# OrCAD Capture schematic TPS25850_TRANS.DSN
size B
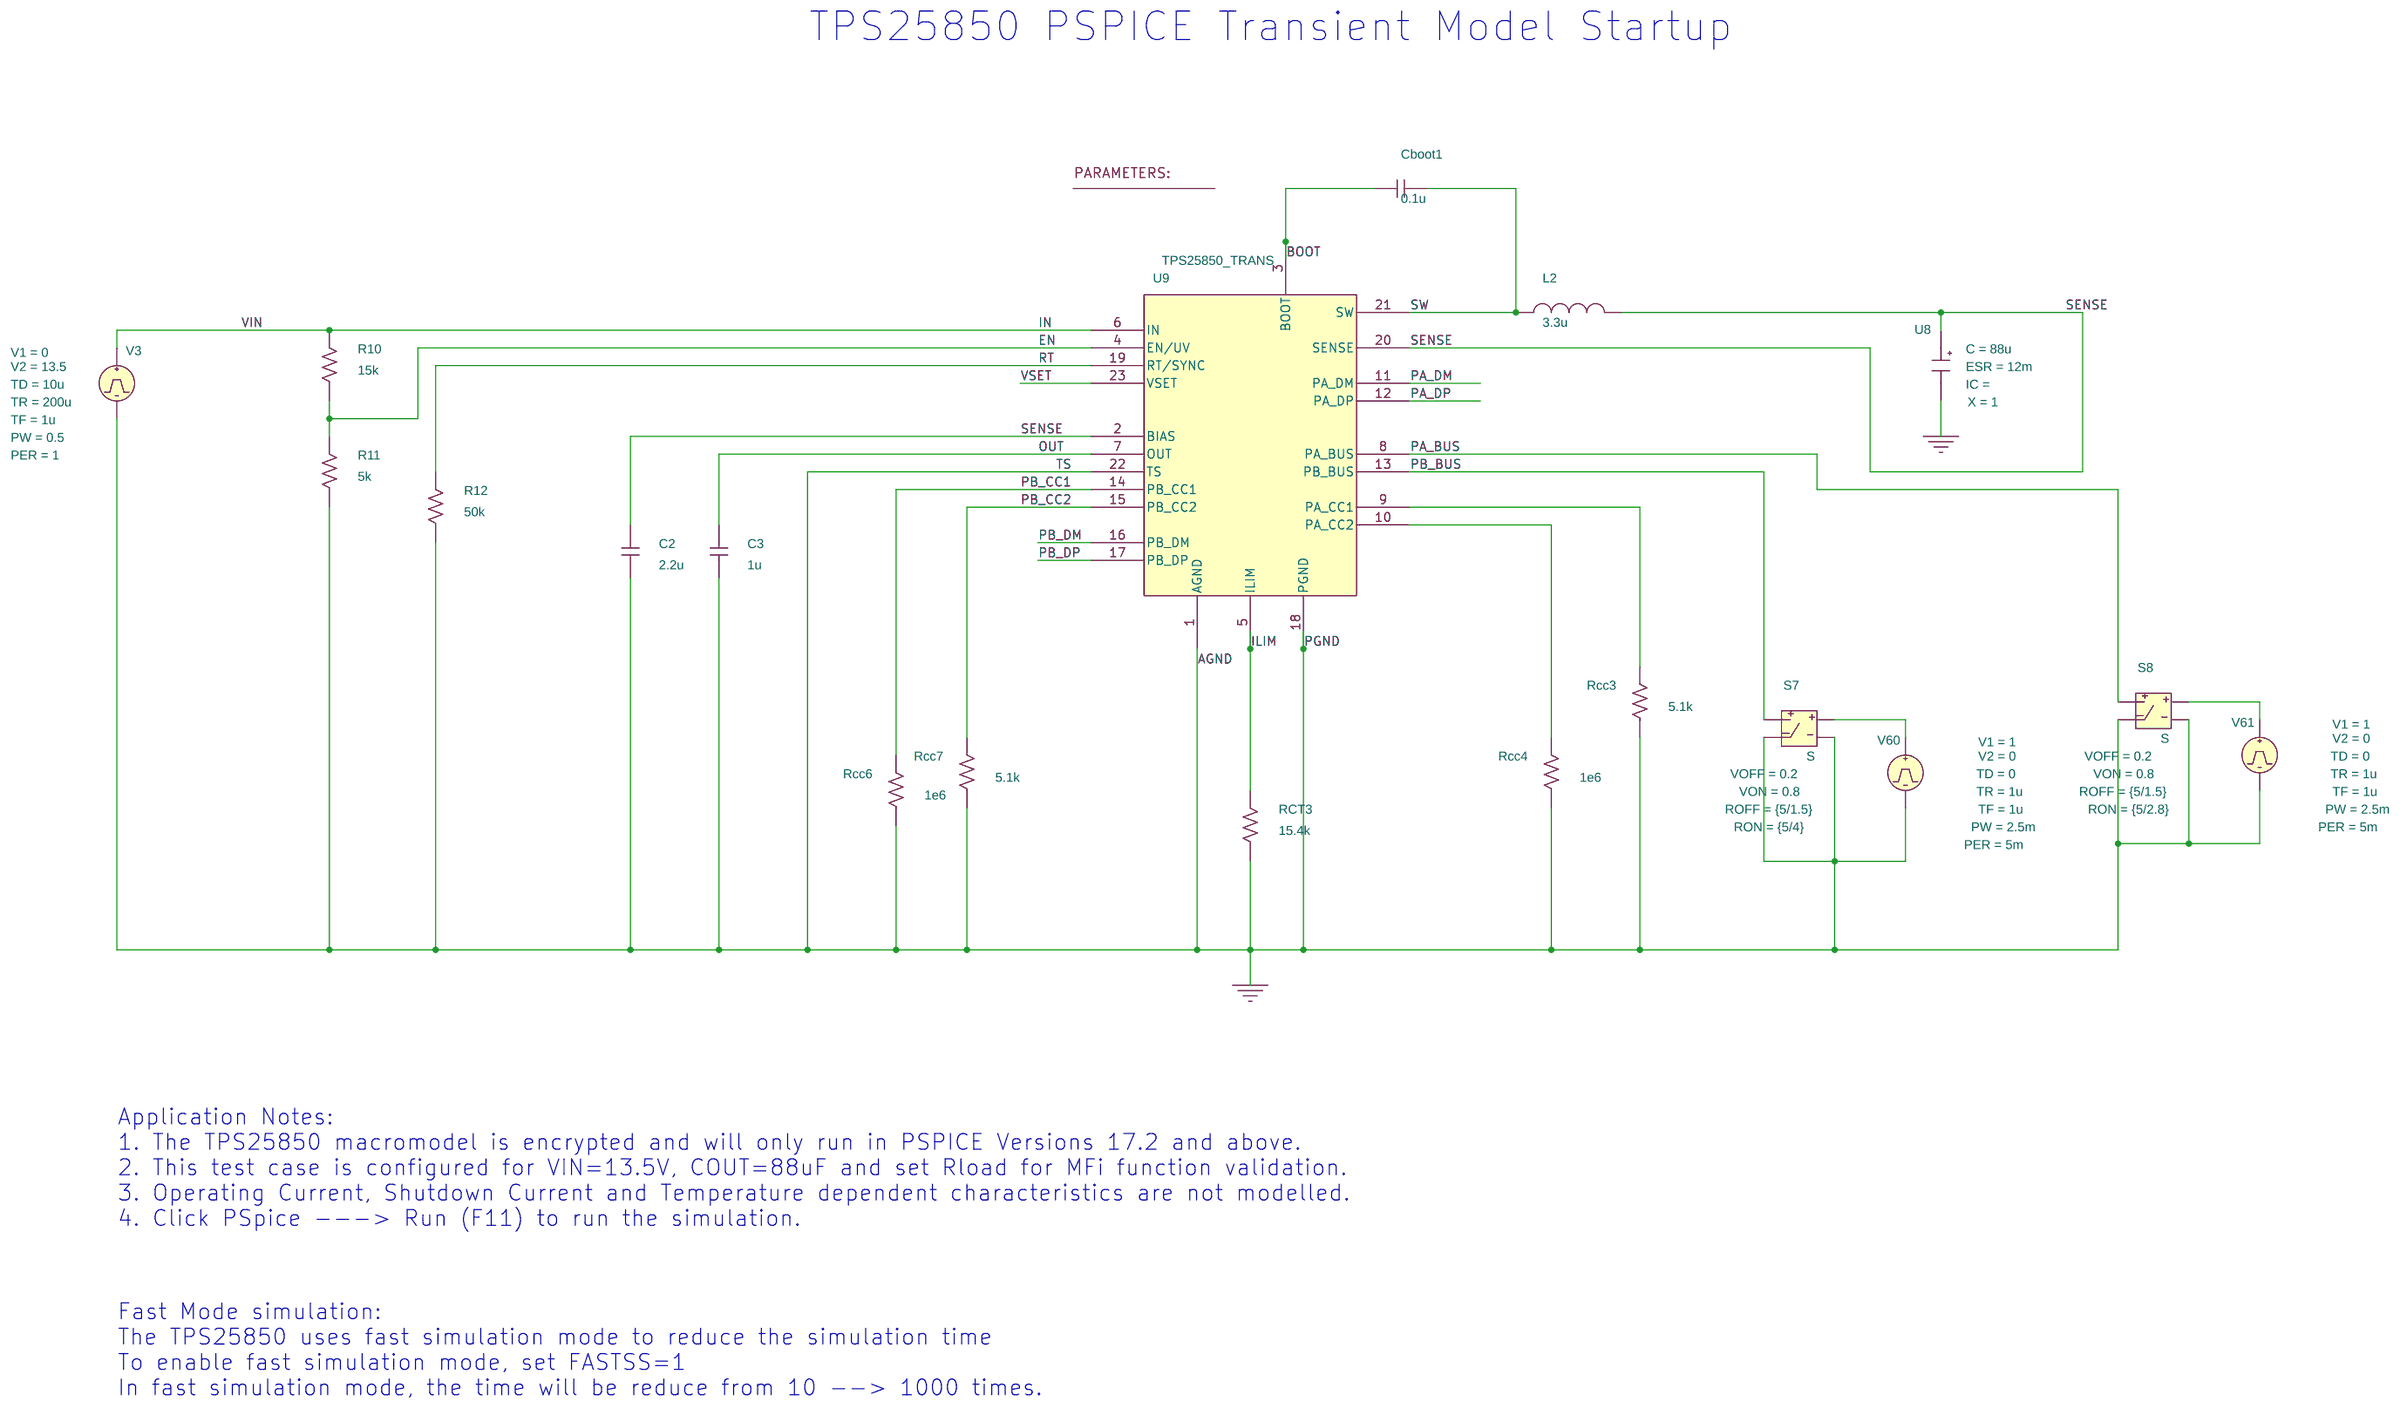
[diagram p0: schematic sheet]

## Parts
1  PARAM
C2  2.2u  [RAD/CK05]
C3  1u  [RAD/CK05]
Cboot1  0.1u  [RAD/CK05]
L2  3.3u  [DISC/.350x.175/LS.200x.100/.034]
R10  15k  [AX/RC05]
R11  5k  [AX/RC05]
R12  50k  [AX/RC05]
Rcc3  5.1k  [AX/RC05]
Rcc4  1e6  [AX/RC05]
Rcc6  1e6  [AX/RC05]
Rcc7  5.1k  [AX/RC05]
RCT3  15.4k  [AX/RC05]
S7  S
S8  S
U8  CESR
U9  TPS25850_TRANS
V3  VPULSE
V60  VPULSE
V61  VPULSE

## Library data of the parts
1 = PARAM: MODE: 0; VIN: 10; VOUTIC: 5
C2 C3 Cboot1 = C
L2 = L
R10-R12 Rcc3 Rcc4 Rcc6 Rcc7 RCT3 = R
S7 = S: ROFF: {5/1.5}; RON: {5/4}; VOFF: 0.2; VON: 0.8
S8 = S: ROFF: {5/1.5}; RON: {5/2.8}; VOFF: 0.2; VON: 0.8
U8 = CESR_0: C: 88u; ESR: 12m; X: 1
U9 = TPS25850_TRANS
V3 = VPULSE: PER: 1; PW: 0.5; TD: 10u; TF: 1u; TR: 200u; V1: 0; V2: 13.5
V60 V61 = VPULSE: PER: 5m; PW: 2.5m; TD: 0; TF: 1u; TR: 1u; V1: 1; V2: 0

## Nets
0: C2.1 C3.1 R11.1 R12.1 Rcc3.1 Rcc4.1 Rcc6.1 Rcc7.1 RCT3.1 S7.1(2) S7.3(4) S8.1(2) S8.3(4) U8.2(OUT) U9.1(AGND) U9.18(PGND) U9.22(TS) V3.2(-) V60.2(-) V61.2(-)
BOOT: Cboot1.1 U9.3(BOOT)
EN: R10.1 R11.2 U9.4(EN/UV)
ILIM: RCT3.2 U9.5(ILIM)
IN: R10.2 U9.6(IN) V3.1(+)
OUT: C3.2 U9.7(OUT)
PA_BUS: S8.2(3) U9.8(PA_BUS)
PA_DM: U9.11(PA_DM)
PA_DP: U9.12(PA_DP)
PB_BUS: S7.2(3) U9.13(PB_BUS)
PB_CC1: Rcc6.2 U9.14(PB_CC1)
PB_CC2: Rcc7.2 U9.15(PB_CC2)
PB_DM: U9.16(PB_DM)
PB_DP: U9.17(PB_DP)
RT: R12.2 U9.19(RT/SYNC)
SENSE: C2.2 L2.2 U8.1(IN) U9.2(BIAS) U9.20(SENSE)
SW: Cboot1.2 L2.1 U9.21(SW)
VSET: U9.23(VSET)
N7635958: Rcc3.2 U9.9(PA_CC1)
N7635972: Rcc4.2 U9.10(PA_CC2)
N7636108: S8.0(1) V61.1(+)
N7636118: S7.0(1) V60.1(+)

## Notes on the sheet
- TPS25850 PSPICE Transient Model Startup
- Application Notes:
  1. The TPS25850 macromodel is encrypted and will only run in PSPICE Versions 17.2 and above.
  2. This test case is configured for VIN=13.5V, COUT=88uF and set Rload for MFi function validation.
  3. Operating Current, Shutdown Current and Temperature dependent characteristics are not modelled.
  4. Click PSpice ---> Run (F11) to run the simulation.
- Fast Mode simulation:
  The TPS25850 uses fast simulation mode to reduce the simulation time
  To enable fast simulation mode, set FASTSS=1
  In fast simulation mode, the time will be reduce from 10 --> 1000 times.
